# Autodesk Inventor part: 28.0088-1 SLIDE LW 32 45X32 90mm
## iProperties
Created: 2007-06
Part Number: 28.0088-1 SLIDE LW 32 45X32 90mm
Material: Aluminum-6061
Document SubType Name: Modeling
Designer: Andy Moles
Density: 2.71 g/cm^3
Author: Andy Moles
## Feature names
1. Extrusion1
2. Extrusion2
